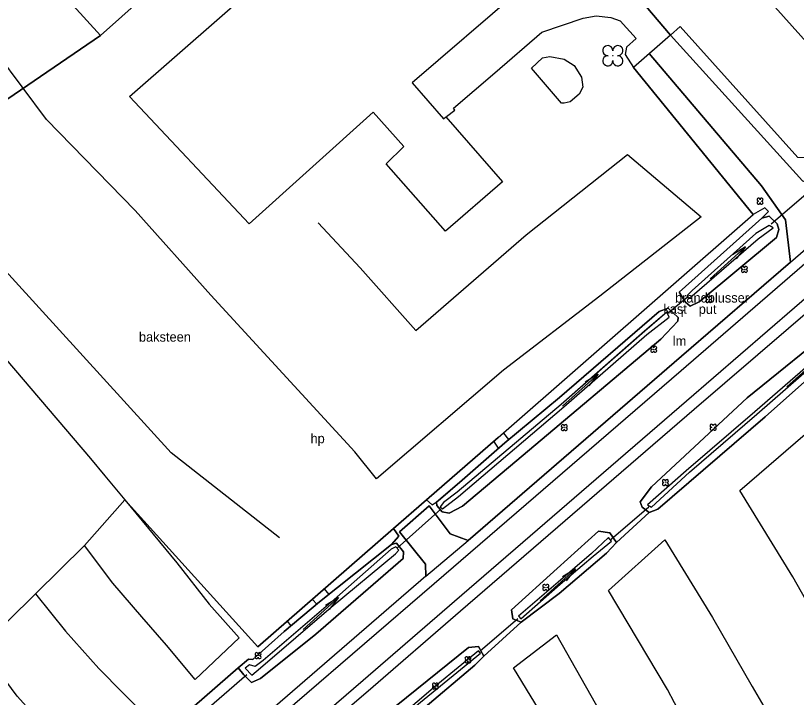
# Model space of a CAD drawing. Extents: x 154825 to 158680, y 370717 to 378075.
# Drawn here: x 156295.9 to 156377.5, y 376421.3 to 376492.5 of the extents above; entities that cross this region are included whole.
import ezdxf

# ---------------------------------------------------------------- set-up
doc = ezdxf.new("R2010")
doc.units = 0
for name, color, linetype in [('baken', 7, 'Continuous'), ('boom', 7, 'Continuous'), ('brandblusser', 7, 'Continuous'), ('cultuurscheiding', 7, 'Continuous'), ('deelstreep(1-1)', 7, 'Continuous'), ('duiker lijn', 7, 'Continuous'), ('gebouw algemeen', 7, 'Continuous'), ('haag geschoren', 7, 'Continuous'), ('hoogtepunt', 7, 'Continuous'), ('hoogteverschillijn', 7, 'Continuous'), ('insteek sloot', 7, 'Continuous'), ('kast_huis punt', 7, 'Continuous'), ('maaiveldlijn algemeen - gesloten verharding', 7, 'Continuous'), ('maaiveldlijn algemeen - open verharding', 7, 'Continuous'), ('maaiveldlijn algemeen - verharding algemeen', 7, 'Continuous'), ('put(deksel) water', 7, 'Continuous'), ('raster - hek', 7, 'Continuous'), ('rioolput(z_inl)', 7, 'Continuous'), ('Sloot bodem', 7, 'Continuous'), ('stroomrichting  watergangen', 7, 'Continuous'), ('verlichtingsobject', 7, 'Continuous'), ('vlak_Grasland', 7, 'Continuous'), ('vlak_Grazige_vegetatie', 7, 'Continuous')]:
    doc.layers.add(name, color=color, linetype=linetype)

msp = doc.modelspace()

# ---------------------------------------------------------------- linework, layer by layer
at = {"layer": 'boom'}
for centre, radius in [((156358.29, 376488.359), 0.02), ((156373.67, 376473.162), 0.006), ((156372.027, 376466.037), 0.006), ((156368.314, 376462.89), 0.006), ((156362.559, 376457.684), 0.006), ((156353.222, 376449.499), 0.006), ((156368.777, 376449.541), 0.006), ((156363.779, 376443.759), 0.006), ((156351.299, 376432.811), 0.006), ((156321.24, 376425.678), 0.006), ((156343.16, 376425.235), 0.006), ((156339.756, 376422.498), 0.006)]:
    msp.add_circle(centre, radius, dxfattribs=at)
for centre, radius, start, end in [((156357.763, 376488.886), 0.528, 357.07502, 272.92498), ((156358.817, 376488.886), 0.528, 267.07502, 182.92498), ((156357.763, 376487.832), 0.528, 87.07502, 2.92498), ((156358.817, 376487.832), 0.528, 177.07502, 92.92498), ((156373.512, 376473.32), 0.158, 357.07502, 272.92498), ((156373.512, 376473.004), 0.158, 87.07502, 2.92498), ((156373.828, 376473.32), 0.158, 267.07502, 182.92498), ((156373.828, 376473.004), 0.158, 177.07502, 92.92498), ((156371.869, 376466.196), 0.158, 357.07502, 272.92498), ((156372.185, 376466.196), 0.158, 267.07502, 182.92498), ((156371.869, 376465.879), 0.158, 87.07502, 2.92498), ((156372.185, 376465.879), 0.158, 177.07502, 92.92498), ((156368.156, 376463.048), 0.158, 357.07502, 272.92498), ((156368.472, 376463.048), 0.158, 267.07502, 182.92498), ((156368.156, 376462.732), 0.158, 87.07502, 2.92498), ((156368.472, 376462.732), 0.158, 177.07502, 92.92498), ((156362.401, 376457.842), 0.158, 357.07502, 272.92498), ((156362.401, 376457.526), 0.158, 87.07502, 2.92498), ((156362.717, 376457.842), 0.158, 267.07502, 182.92498), ((156362.717, 376457.526), 0.158, 177.07502, 92.92498), ((156353.064, 376449.658), 0.158, 357.07502, 272.92498), ((156353.064, 376449.341), 0.158, 87.07502, 2.92498), ((156353.38, 376449.658), 0.158, 267.07502, 182.92498), ((156353.38, 376449.341), 0.158, 177.07502, 92.92498), ((156368.619, 376449.699), 0.158, 357.07502, 272.92498), ((156368.619, 376449.383), 0.158, 87.07502, 2.92498), ((156368.935, 376449.699), 0.158, 267.07502, 182.92498), ((156368.935, 376449.383), 0.158, 177.07502, 92.92498), ((156363.621, 376443.917), 0.158, 357.07502, 272.92498), ((156363.621, 376443.601), 0.158, 87.07502, 2.92498), ((156363.937, 376443.917), 0.158, 267.07502, 182.92498), ((156363.937, 376443.601), 0.158, 177.07502, 92.92498), ((156351.141, 376432.969), 0.158, 357.07502, 272.92498), ((156351.457, 376432.969), 0.158, 267.07502, 182.92498), ((156351.141, 376432.652), 0.158, 87.07502, 2.92498), ((156351.457, 376432.652), 0.158, 177.07502, 92.92498), ((156321.082, 376425.836), 0.158, 357.07502, 272.92498), ((156321.082, 376425.52), 0.158, 87.07502, 2.92498), ((156321.398, 376425.836), 0.158, 267.07502, 182.92498), ((156321.398, 376425.52), 0.158, 177.07502, 92.92498), ((156343.002, 376425.393), 0.158, 357.07502, 272.92498), ((156343.002, 376425.077), 0.158, 87.07502, 2.92498), ((156343.318, 376425.393), 0.158, 267.07502, 182.92498), ((156343.318, 376425.077), 0.158, 177.07502, 92.92498), ((156339.598, 376422.656), 0.158, 357.07502, 272.92498), ((156339.598, 376422.34), 0.158, 87.07502, 2.92498), ((156339.914, 376422.656), 0.158, 267.07502, 182.92498), ((156339.914, 376422.34), 0.158, 177.07502, 92.92498)]:
    msp.add_arc(centre, radius, start, end, dxfattribs=at)
at = {"layer": 'cultuurscheiding'}
for points in [[(156280.45, 376473.85), (156304.77, 376490.48)], [(156321.216, 376426.586), (156307.32, 376441.96)], [(156358.675, 376437.488), (156362.08, 376440.641)], [(156344.802, 376425.636), (156348.733, 376429.163)], [(156314.55, 376420.392), (156319.146, 376424.398)]]:
    msp.add_lwpolyline(points, dxfattribs=at)
at = {"layer": 'deelstreep(1-1)'}
for points in [[(156516.831, 376582.622), (156511.001, 376577.536), (156493.7, 376562.56), (156474.596, 376546.084), (156453.196, 376527.604), (156434.782, 376511.754), (156416.826, 376496.176), (156407.988, 376488.584), (156398.633, 376480.476), (156385.724, 376469.313), (156365.992, 376452.264), (156341.764, 376431.348), (156332.221, 376423.093), (156319.308, 376411.937), (156302.65, 376397.565), (156288.291, 376385.163), (156270.134, 376369.483), (156252.686, 376354.407), (156230.715, 376335.358), (156215.589, 376322.293), (156199.581, 376308.448), (156183.792, 376294.705), (156174.038, 376286.04)], [(156396.638, 376482.436), (156384.498, 376471.951), (156365.428, 376455.448), (156339.636, 376433.192), (156325.079, 376420.638), (156318.266, 376414.744), (156309.764, 376407.44), (156295.488, 376395.088), (156278.817, 376380.652), (156257.66, 376362.335), (156243.998, 376350.503), (156228.738, 376337.374), (156210.532, 376321.663), (156193.879, 376307.213), (156180.981, 376295.953), (156172.674, 376288.565)]]:
    msp.add_lwpolyline(points, dxfattribs=at)
at = {"layer": 'duiker lijn'}
for points in [[(156381.133, 376476.145), (156374.829, 376470.765)], [(156366.049, 376463.103), (156364.086, 376461.442)], [(156362.06, 376441.186), (156358.134, 376437.817)], [(156340.32, 376440.998), (156335.753, 376436.919)], [(156348.385, 376429.506), (156344.443, 376426.135)], [(156320.054, 376423.658), (156315.315, 376419.555)]]:
    msp.add_lwpolyline(points, dxfattribs=at)
at = {"layer": 'gebouw algemeen'}
msp.add_lwpolyline([(156340.61, 376481.762), (156340.859, 376481.978), (156346.751, 376475.172), (156340.814, 376470.03), (156334.619, 376477.073), (156336.475, 376478.855), (156333.276, 376482.455), (156320.32, 376470.776), (156307.805, 376484.106), (156336.284, 376509.047), (156348.432, 376495.116), (156337.323, 376485.541), (156337.323, 376485.541), (156340.61, 376481.762)], dxfattribs=at)
msp.add_lwpolyline([(156306.63, 376507), (156313.99, 376498.73), (156304.77, 376490.48), (156297.29, 376498.71)], close=True, dxfattribs=at)
at = {"layer": 'haag geschoren'}
for points in [[(156373.838, 376471.367), (156374.534, 376472.071), (156374.161, 376472.459), (156372.958, 376471.776)], [(156346.86, 376448.933), (156347.4, 376448.249)], [(156346.351, 376447.348), (156345.871, 376448.07)], [(156338.833, 376441.947), (156339.411, 376441.427), (156340.052, 376441.835)], [(156335.177, 376437.289), (156335.941, 376438.175), (156335.398, 376438.959)], [(156328.648, 376432.076), (156328.166, 376432.65)], [(156327.376, 376431.05), (156326.91, 376431.554)], [(156324.287, 376429.265), (156324.673, 376428.806)]]:
    msp.add_lwpolyline(points, dxfattribs=at)
at = {"layer": 'hoogteverschillijn'}
for points in [[(156352.33, 376517.12), (156372.18, 376496.89), (156382.76, 376485.02)], [(156323.49, 376437.98), (156312.17, 376446.85), (156293.39, 376467.46), (156288.87, 376474.65), (156284.15, 376482.34), (156279.5, 376488.57), (156273.37, 376495.93), (156266.98, 376503.25), (156261.04, 376509.98)], [(156327.53, 376470.89), (156331.89, 376466.2), (156337.73, 376459.66), (156349.25, 376469.64), (156359.84, 376478.04), (156367.52, 376471.51), (156356.92, 376463.22), (156346.88, 376455.52), (156333.61, 376444.15), (156331.35, 376446.97), (156316.29, 376463.34), (156308.39, 376472.18), (156299.14, 376481.7), (156291.49, 376491.94)], [(156294.88, 376456.64), (156303.73, 376446.28), (156305.25, 376444.48), (156307.32, 376441.96), (156312.76, 376435.36), (156316.14, 376431.05), (156319.26, 376427.55), (156314.67, 376423.2), (156311.67, 376426.76), (156309.09, 376429.73), (156306.07, 376433.26), (156303.12, 376437.17), (156297.99, 376432.13), (156301.14, 376428.24), (156304.6, 376424.35), (156309.67, 376419.2)], [(156381.16, 376426.69), (156377.09, 376433.91), (156371.57, 376442.92), (156380.41, 376450.57)], [(156379.66, 376397.34), (156373.49, 376406.72), (156369.13, 376412.39), (156364.01, 376422.13), (156357.83, 376432.48), (156363.74, 376437.76), (156368.7, 376429.67), (156372.83, 376422.46), (156377.47, 376414.52)], [(156325.38, 376406.37), (156330.27, 376397.52), (156335.03, 376387.82), (156344.43, 376394.15), (156339.96, 376402.94), (156334.76, 376413.29), (156341.25, 376418.91), (156346.13, 376409.6), (156351.69, 376399.5), (156359.5, 376405.2), (156354.59, 376413.42), (156347.9, 376424.4), (156352.42, 376427.86), (156358.52, 376417.03), (156363.19, 376407.47), (156374.61, 376391.22), (156381.76, 376379.89)], [(156299.67, 376417.47), (156296.08, 376421.43), (156292.28, 376426.52), (156287.16, 376421.49), (156289.59, 376418.14)]]:
    msp.add_lwpolyline(points, dxfattribs=at)
at = {"layer": 'insteek sloot'}
for points in [[(156397.714, 376470.437), (156398.163, 376471.433), (156397.507, 376472.382), (156395.764, 376472.679), (156386.737, 376464.913), (156381.959, 376460.411), (156372.311, 376452.628), (156362.32, 376443.315), (156361.135, 376441.742), (156361.34, 376441.193), (156362.08, 376440.641)], [(156373.838, 376471.367), (156365.226, 376463.664), (156365.879, 376462.615), (156366.384, 376462.192), (156367.32, 376462.649), (156375.398, 376469.362), (156375.638, 376470.191), (156375.446, 376470.783), (156374.635, 376471.602), (156373.838, 376471.367)], [(156362.08, 376440.641), (156362.997, 376440.977), (156374.206, 376450.62), (156381.121, 376456.779), (156396.011, 376469.147), (156396.636, 376469.621), (156397.714, 376470.437)], [(156339.857, 376441.665), (156339.913, 376441.361), (156340.455, 376440.704), (156341.185, 376440.569), (156342.601, 376441.306), (156348.942, 376446.633), (156363.307, 376458.757), (156365.095, 376460.61), (156365.119, 376461.008), (156364.058, 376461.989), (156363.115, 376461.64), (156352.718, 376452.65), (156347.007, 376447.924), (156342.552, 376444.012), (156339.857, 376441.665)], [(156358.675, 376437.488), (156357.996, 376438.494), (156356.812, 376438.67), (156352.465, 376434.786), (156347.723, 376430.466), (156347.862, 376429.521), (156348.733, 376429.163)], [(156319.146, 376424.398), (156319.767, 376423.664), (156320.54, 376422.86), (156321.498, 376423.298), (156327.28, 376427.919), (156336.386, 376435.835), (156336.439, 376436.516), (156335.712, 376437.423), (156335.177, 376437.289)], [(156335.177, 376437.289), (156327.669, 376431.294), (156323.956, 376428.21), (156320.7, 376425.264), (156320.248, 376425.301), (156319.146, 376424.398)], [(156348.733, 376429.163), (156352.683, 376432.156), (156357.64, 376436.376), (156358.675, 376437.488)], [(156307.034, 376392.406), (156301.554, 376387.749), (156299.054, 376385.673), (156298.055, 376385.226), (156297.004, 376386.445), (156297.286, 376387.624), (156303.708, 376393.203), (156321.161, 376408.216), (156334.598, 376419.552), (156343.226, 376426.534), (156344.259, 376426.619), (156344.802, 376425.636)], [(156319.742, 376404.012), (156333.51, 376415.92), (156343.877, 376424.679), (156344.802, 376425.636)]]:
    msp.add_lwpolyline(points, dxfattribs=at)
at = {"layer": 'maaiveldlijn algemeen - gesloten verharding'}
for points in [[(156237.378, 376339.604), (156253.188, 376353.259), (156271.076, 376368.682), (156289.082, 376384.275), (156303.762, 376396.95), (156320.092, 376411.161), (156332.733, 376421.992), (156342.374, 376430.345), (156366.772, 376451.412), (156386.501, 376468.348), (156394.774, 376475.56), (156398.533, 376478.836)], [(156376.85, 376466.776), (156383.948, 376472.951)], [(156343.173, 376437.713), (156365.451, 376456.953), (156376.85, 376466.776)], [(156338.773, 376433.979), (156343.173, 376437.713)], [(156338.773, 376433.979), (156324.326, 376421.491), (156317.461, 376415.563), (156308.883, 376408.18), (156294.847, 376396.042), (156278.318, 376381.714)]]:
    msp.add_lwpolyline(points, dxfattribs=at)
at = {"layer": 'maaiveldlijn algemeen - open verharding'}
for points in [[(156364.32, 376490.521), (156378.115, 376475.292), (156383.948, 376472.951)], [(156376.85, 376466.776), (156376.317, 376471.199), (156373.805, 376474.759), (156362.096, 376488.572)], [(156338.773, 376433.979), (156338.733, 376435.234), (156336.016, 376438.607), (156339.095, 376441.327), (156341.301, 376438.41), (156343.173, 376437.713)]]:
    msp.add_lwpolyline(points, dxfattribs=at)
at = {"layer": 'maaiveldlijn algemeen - verharding algemeen'}
for points in [[(156325.824, 376536.25), (156329.711, 376533.204), (156330.858, 376534.227), (156335.661, 376528.85), (156336.449, 376529.442), (156339.573, 376521.795), (156342.889, 376515.19), (156351.182, 376507.189), (156355.852, 376501.933), (156355.234, 376501.241), (156364.32, 376490.521)], [(156340.929, 376482.007), (156341.796, 376482.677), (156341.651, 376482.874), (156345.956, 376486.578), (156350.881, 376490.813), (156355.182, 376492.274), (156356.56, 376492.508), (156358.076, 376492.345), (156359.044, 376491.988), (156360.735, 376490.146), (156359.721, 376489.261), (156359.577, 376488.489), (156360.435, 376487.117)], [(156349.794, 376487.065), (156350.943, 376488.151), (156351.705, 376488.284), (156353.204, 376487.993), (156354.26, 376487.346), (156355.009, 376486.108), (156355.173, 376485.069), (156354.791, 376484.354), (156353.846, 376483.55), (156353.216, 376483.388), (156352.942, 376483.409), (156349.794, 376487.065)]]:
    msp.add_lwpolyline(points, dxfattribs=at)
at = {"layer": 'raster - hek'}
for points in [[(156379.75, 376477.628), (156377.621, 376477.731), (156365.335, 376491.41), (156364.32, 376490.521)], [(156364.32, 376490.521), (156360.435, 376487.117)], [(156360.435, 376487.117), (156372.958, 376471.776)], [(156346.311, 376448.452), (156372.958, 376471.776)], [(156346.311, 376448.452), (156335.472, 376439.024), (156321.216, 376426.586)], [(156346.311, 376448.452), (156338.833, 376441.947), (156335.398, 376438.959)], [(156335.398, 376438.959), (156321.216, 376426.586)]]:
    msp.add_lwpolyline(points, dxfattribs=at)
at = {"layer": 'Sloot bodem'}
for points in [[(156397.631, 376471.341), (156397.218, 376471.793), (156395.216, 376469.919), (156384.715, 376461.205), (156373.136, 376451.165), (156365.95, 376444.972), (156361.915, 376441.45), (156362.332, 376441.174), (156366.287, 376444.832), (156373.326, 376450.916), (156385.594, 376461.589), (156395.556, 376469.565), (156397.631, 376471.341)], [(156375.026, 376470.363), (156374.612, 376470.625), (156373.221, 376469.767), (156366.563, 376463.82), (156366.03, 376463.277), (156366.194, 376463.005), (156366.589, 376463.278), (156373.469, 376469.227), (156375.026, 376470.363)], [(156364.181, 376461.041), (156363.92, 376461.58), (156361.616, 376459.595), (156352.905, 376451.922), (156342.029, 376442.76), (156340.605, 376441.677), (156340.261, 376441.23), (156340.503, 376441.029), (156342.167, 376442.313), (156353.182, 376451.679), (156361.836, 376459.233), (156364.181, 376461.041)], [(156358.165, 376437.632), (156357.852, 376438.006), (156356.068, 376436.336), (156352.599, 376433.356), (156348.434, 376429.794), (156348.698, 376429.51), (156352.785, 376433.136), (156356.248, 376436.067), (156358.165, 376437.632)], [(156335.936, 376436.687), (156335.612, 376437.038), (156335.138, 376436.795), (156328.604, 376431.013), (156321.77, 376425.165), (156320.926, 376424.551), (156320.338, 376424.708), (156319.897, 376424.363), (156320.604, 376423.644), (156321.509, 376424.402), (156328.873, 376430.727), (156335.598, 376436.311), (156335.936, 376436.687)], [(156333.797, 376417.378), (156328.216, 376412.782), (156315.586, 376401.799), (156302.618, 376390.616), (156298.728, 376387.131), (156297.963, 376386.551), (156297.682, 376386.069), (156297.975, 376385.794), (156298.275, 376386.012), (156298.788, 376386.5), (156302.658, 376390.208), (156316.803, 376402.349), (156328.381, 376412.57), (156333.959, 376417.22), (156338.219, 376420.806), (156344.466, 376425.948), (156344.256, 376426.195), (156340.026, 376422.68), (156333.797, 376417.378)]]:
    msp.add_lwpolyline(points, dxfattribs=at)
at = {"layer": 'stroomrichting  watergangen'}
for p, q in [((156368.445, 376465.05), (156372.153, 376468.394)), ((156372.132, 376468.394), (156370.794, 376467.556)), ((156372.153, 376468.394), (156371.182, 376467.149)), ((156376.465, 376453.759), (156380.173, 376457.103)), ((156353.049, 376451.758), (156356.757, 376455.101)), ((156356.737, 376455.102), (156355.398, 376454.264)), ((156356.757, 376455.101), (156355.786, 376453.856)), ((156350.69, 376431.401), (156354.398, 376434.745)), ((156354.377, 376434.745), (156353.039, 376433.907)), ((156354.398, 376434.745), (156353.427, 376433.499)), ((156325.936, 376428.404), (156329.644, 376431.748)), ((156329.624, 376431.748), (156328.285, 376430.91)), ((156329.644, 376431.748), (156328.673, 376430.503))]:
    msp.add_line(p, q, dxfattribs=at)
at = {"layer": 'vlak_Grasland'}
for points in [[(156377.621, 376477.731), (156365.335, 376491.41), (156364.32, 376490.521), (156355.234, 376501.241)], [(156297.29, 376498.71), (156304.77, 376490.48), (156280.45, 376473.85)], [(156381.76, 376379.89), (156374.61, 376391.22), (156363.19, 376407.47), (156359.5, 376405.2), (156351.69, 376399.5), (156344.43, 376394.15), (156335.03, 376387.82), (156330.265, 376384.272), (156324.394, 376396.131), (156321.17, 376402.546), (156319.742, 376404.012), (156333.51, 376415.92), (156343.877, 376424.679), (156344.802, 376425.636), (156348.734, 376429.163), (156352.683, 376432.156), (156357.64, 376436.376), (156358.675, 376437.488), (156362.08, 376440.641), (156362.997, 376440.977), (156374.206, 376450.62), (156381.121, 376456.779)], [(156281.96, 376416.22), (156287.16, 376421.49), (156292.28, 376426.52), (156297.99, 376432.13), (156303.12, 376437.17), (156307.32, 376441.96), (156321.216, 376426.586), (156335.398, 376438.959), (156335.94, 376438.175), (156335.177, 376437.289), (156327.669, 376431.294), (156323.956, 376428.21), (156320.7, 376425.264), (156320.248, 376425.301), (156319.146, 376424.398), (156314.55, 376420.392)]]:
    msp.add_lwpolyline(points, dxfattribs=at)
at = {"layer": 'vlak_Grazige_vegetatie'}
for points in [[(156378.115, 376475.292), (156364.32, 376490.521), (156365.335, 376491.41), (156377.621, 376477.731)], [(156314.55, 376420.392), (156319.146, 376424.398), (156319.767, 376423.664), (156320.54, 376422.86), (156321.498, 376423.298), (156327.28, 376427.918), (156336.387, 376435.835), (156336.439, 376436.516), (156335.712, 376437.423), (156335.177, 376437.289), (156335.94, 376438.175), (156335.398, 376438.959), (156338.833, 376441.947), (156346.311, 376448.452), (156372.958, 376471.776), (156360.435, 376487.117), (156362.096, 376488.572), (156373.805, 376474.759), (156376.317, 376471.199), (156376.85, 376466.776), (156365.451, 376456.953), (156343.173, 376437.713), (156341.301, 376438.41), (156339.095, 376441.327), (156336.016, 376438.607), (156338.733, 376435.234), (156338.773, 376433.979), (156324.326, 376421.491), (156317.461, 376415.563)], [(156320.092, 376411.161), (156332.733, 376421.992), (156342.374, 376430.345), (156366.772, 376451.412), (156386.501, 376468.348)], [(156381.959, 376460.411), (156372.311, 376452.628), (156362.32, 376443.315), (156361.135, 376441.742), (156361.34, 376441.193), (156362.08, 376440.641), (156358.675, 376437.488), (156357.995, 376438.494), (156356.812, 376438.67), (156352.466, 376434.786), (156347.723, 376430.466), (156347.862, 376429.521), (156348.734, 376429.163), (156344.802, 376425.636), (156344.259, 376426.62), (156343.226, 376426.534), (156334.598, 376419.552)]]:
    msp.add_lwpolyline(points, dxfattribs=at)
for points in [[(156397.507, 376472.382), (156398.163, 376471.433), (156397.714, 376470.437), (156396.636, 376469.621), (156396.011, 376469.147), (156381.121, 376456.779), (156374.206, 376450.62), (156362.997, 376440.977), (156362.08, 376440.641), (156361.34, 376441.193), (156361.135, 376441.742), (156362.32, 376443.315), (156372.311, 376452.628), (156381.959, 376460.411), (156386.738, 376464.913), (156395.764, 376472.679)], [(156361.915, 376441.45), (156362.332, 376441.174), (156366.287, 376444.832), (156373.326, 376450.916), (156385.594, 376461.589), (156395.556, 376469.565), (156397.631, 376471.341), (156397.218, 376471.793), (156395.216, 376469.919), (156384.715, 376461.205), (156373.136, 376451.165), (156365.95, 376444.972)], [(156365.879, 376462.615), (156366.383, 376462.192), (156367.32, 376462.649), (156375.398, 376469.362), (156375.638, 376470.19), (156375.446, 376470.783), (156374.635, 376471.602), (156373.838, 376471.367), (156365.226, 376463.664)], [(156375.446, 376470.783), (156375.638, 376470.19), (156375.398, 376469.362), (156367.32, 376462.649), (156366.383, 376462.192), (156365.879, 376462.615), (156365.226, 376463.664), (156373.838, 376471.367), (156374.635, 376471.602)], [(156366.03, 376463.277), (156366.194, 376463.005), (156366.589, 376463.278), (156373.469, 376469.227), (156375.026, 376470.363), (156374.612, 376470.625), (156373.222, 376469.767), (156366.563, 376463.82)], [(156339.913, 376441.361), (156340.455, 376440.703), (156341.185, 376440.569), (156342.601, 376441.306), (156348.942, 376446.633), (156363.307, 376458.757), (156365.095, 376460.61), (156365.119, 376461.008), (156364.058, 376461.989), (156363.115, 376461.64), (156352.718, 376452.65), (156347.007, 376447.924), (156342.552, 376444.012), (156340.052, 376441.835), (156339.858, 376441.665)], [(156364.058, 376461.989), (156365.119, 376461.008), (156365.095, 376460.61), (156363.307, 376458.757), (156348.942, 376446.633), (156342.601, 376441.306), (156341.185, 376440.569), (156340.455, 376440.703), (156339.913, 376441.361), (156339.858, 376441.665), (156340.052, 376441.835), (156342.552, 376444.012), (156347.007, 376447.924), (156352.718, 376452.65), (156363.115, 376461.64)], [(156340.261, 376441.23), (156340.503, 376441.029), (156342.167, 376442.313), (156353.183, 376451.679), (156361.836, 376459.233), (156364.181, 376461.041), (156363.92, 376461.58), (156361.617, 376459.595), (156352.905, 376451.922), (156342.029, 376442.76), (156340.604, 376441.677)], [(156357.995, 376438.494), (156358.675, 376437.488), (156357.64, 376436.376), (156352.683, 376432.156), (156348.734, 376429.163), (156347.862, 376429.521), (156347.723, 376430.466), (156352.466, 376434.786), (156356.812, 376438.67)], [(156348.433, 376429.794), (156348.698, 376429.51), (156352.785, 376433.136), (156356.248, 376436.067), (156358.165, 376437.632), (156357.852, 376438.006), (156356.068, 376436.336), (156352.599, 376433.356)], [(156335.712, 376437.423), (156336.439, 376436.516), (156336.387, 376435.835), (156327.28, 376427.918), (156321.498, 376423.298), (156320.54, 376422.86), (156319.767, 376423.664), (156319.146, 376424.398), (156320.248, 376425.301), (156320.7, 376425.264), (156323.956, 376428.21), (156327.669, 376431.294), (156335.177, 376437.289)], [(156328.604, 376431.013), (156321.77, 376425.165), (156320.927, 376424.551), (156320.338, 376424.708), (156319.897, 376424.363), (156320.604, 376423.644), (156321.509, 376424.402), (156328.873, 376430.727), (156335.598, 376436.311), (156335.936, 376436.687), (156335.612, 376437.038), (156335.138, 376436.795)], [(156344.259, 376426.62), (156344.802, 376425.636), (156343.877, 376424.679), (156333.51, 376415.92), (156319.742, 376404.012), (156318.914, 376403.205), (156307.034, 376392.406), (156301.554, 376387.749), (156299.054, 376385.673), (156298.055, 376385.226), (156297.004, 376386.445), (156297.286, 376387.624), (156303.708, 376393.203), (156321.161, 376408.216), (156334.598, 376419.552), (156343.226, 376426.534)], [(156297.682, 376386.069), (156297.975, 376385.794), (156298.275, 376386.012), (156298.788, 376386.5), (156302.658, 376390.208), (156316.803, 376402.349), (156328.381, 376412.57), (156333.959, 376417.22), (156338.219, 376420.806), (156344.466, 376425.948), (156344.256, 376426.195), (156340.026, 376422.68), (156333.797, 376417.378), (156328.216, 376412.782), (156315.586, 376401.799), (156302.617, 376390.616), (156298.728, 376387.131), (156297.963, 376386.551)]]:
    msp.add_lwpolyline(points, close=True, dxfattribs=at)

# ---------------------------------------------------------------- texts
at = {"layer": 'baken'}
msp.add_text('baksteen', height=1, dxfattribs=at).set_placement((156308.794, 376458.481))
at = {"layer": 'brandblusser'}
msp.add_text('brandblusser', height=1, dxfattribs=at).set_placement((156364.784, 376462.57))
at = {"layer": 'hoogtepunt'}
msp.add_text('hp', height=1, dxfattribs=at).set_placement((156326.716, 376447.868))
at = {"layer": 'kast_huis punt'}
msp.add_text('kast', height=1, dxfattribs=at).set_placement((156363.566, 376461.401))
at = {"layer": 'put(deksel) water'}
msp.add_text('put', height=1, dxfattribs=at).set_placement((156367.264, 376461.383))
at = {"layer": 'rioolput(z_inl)'}
msp.add_text('r', height=1, dxfattribs=at).set_placement((156365.393, 376461.044))
at = {"layer": 'verlichtingsobject'}
msp.add_text('lm', height=1, dxfattribs=at).set_placement((156364.555, 376458.046))

doc.saveas('drawing.dxf')
